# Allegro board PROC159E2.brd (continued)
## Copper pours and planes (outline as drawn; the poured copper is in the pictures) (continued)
DGND on L08_SIG2 (solid shape): 54.38,11.17 54.47,11.11 54.45,11 50.75,7.3 50.67,7.3 50.59,7.35 50.58,7.44 50.58,7.77 50.32,7.98 50.25,8.05 50.27,8.15 52.55,10.43 52.65,10.45 52.72,10.37 53.37,10.17 53.16,10.82 53.08,10.88 53.11,10.99 53.29,11.17
DGND on L08_SIG2 (solid shape): 27.02,32.83 27.11,32.78 27.11,32.68 27.05,32.42 27.18,32.18 27.18,31.84 28.86,30.15 28.89,30.04 28.79,29.98 26.95,29.98 26.86,30.03 26.86,30.14 26.54,30.72 26.22,30.14 26.22,30.03 26.13,29.98 26.05,29.98 24.56,28.49 24.45,28.47 24.39,28.57 24.39,30.43 26.8,32.83
DGND on L08_SIG2 (solid shape): 78.73,45.71 78.8,45.81 78.91,45.79 79.86,44.83 79.86,44.53 79.6,44.53 79.5,44.51 79.42,44.46 79.29,44.32 79.24,44.24 79.22,44.15 79.22,43.96 79.24,43.86 79.29,43.78 79.44,43.63 79.46,43.59 79.44,43.55 79.42,43.54 79.29,43.41 79.24,43.33 79.22,43.23 79.22,43.04 79.24,42.95 79.29,42.87 79.44,42.72 79.46,42.68 79.44,42.64 79.42,42.63 79.29,42.49 79.24,42.41 79.22,42.32 79.22,42.13 79.24,42.03 79.29,41.95 79.44,41.8 79.46,41.76 79.44,41.73 79.42,41.71 79.22,41.51 79.22,41.21 79.24,41.12 79.29,41.04 79.5,40.83 79.86,40.83 79.86,39.87 79.8,39.77 79.69,39.79 78.73,40.75
DGND on L08_SIG2 (solid shape): 80.38,42.49 80.45,42.48 80.58,42.44 80.71,42.44 80.8,42.42 80.84,42.34 80.84,41.48 82.43,39.9 82.43,37.98 82.36,37.89 82.25,37.91 80.89,39.28 80.86,39.37 80.92,39.44 81.09,39.99 80.53,40.09 80.42,40.08 80.36,40.17 80.36,41.05 80.1,41.31 80.29,41.49 80.34,41.58 80.36,41.67 80.36,41.86 80.34,41.96 80.29,42.04 80.16,42.17 80.1,42.22 80.29,42.41 80.32,42.44
DGND on L08_SIG2 (solid shape): 84.84,91.48 84.9,91.49 84.93,91.45 84.93,85.26 82.93,83.26 82.93,82.49 82.87,82.4 82.76,82.41 82.58,82.48 82.38,82.46 82.29,82.47 82.24,82.55 82.24,83.22 82.29,83.3 82.38,83.31 82.9,83.67 82.38,84.03 82.29,84.04 82.24,84.12 82.24,84.34 82.62,84.72 82.62,88.02 82.37,88.26 82.36,88.32 82.41,88.35 82.48,88.35 82.8,88.67 82.8,91.28 82.95,91.43 84.79,91.43
DGND on L08_SIG2 (solid shape): 65.49,30.22 65.56,30.31 65.67,30.29 66.3,29.65 66.33,29.55 66.25,29.48 66.03,29.35 65.95,29.1 65.95,29.08 64.94,28.07 64.94,26.28 63.93,25.27 61.98,25.27 61.88,25.34 61.91,25.45 64.15,27.69 64.15,28.78 64.64,29.26 64.7,29.26 64.8,29.2 64.78,29.09 64.28,28.59 64.28,27.12 63.9,26.74 63.88,26.74 63.61,26.09 64.26,26.36 64.26,26.38 64.78,26.91 64.78,28.39 65.49,29.1
DGND on L08_SIG2 (solid shape): 87.27,25.9 87.33,26 87.44,25.97 91.9,21.51 91.9,20.42 91.98,20.34 92,20.23 91.91,20.17 91.53,20.17 90.67,21.02 90.88,21.23 90.93,21.31 90.95,21.4 90.95,21.59 90.93,21.69 90.88,21.77 90.74,21.9 90.66,21.95 90.57,21.97 90.3,21.97 90.3,22.05 90.3,22.24 90.28,22.33 90.23,22.41 90.09,22.55 90.01,22.6 89.92,22.62 89.65,22.62 89.66,22.69 89.66,22.88 89.64,22.98 89.58,23.06 89.45,23.19 89.37,23.25 89.27,23.27 89.01,23.27 89.01,23.34 89.01,23.53 88.99,23.63 88.94,23.71 88.8,23.84 88.72,23.89 88.63,23.91 88.36,23.91 88.36,23.99 88.36,24.28 88.16,24.49 88.07,24.54 87.98,24.56 87.69,24.56 87.4,24.28 87.33,24.28 87.27,24.34
DGND on L08_SIG2 (solid shape): 105.05,84.35 105.16,84.38 105.23,84.28 105.23,83.67 103.9,82.34 103.81,82.31 103.74,82.36 103.14,82.43 103.21,81.84 103.26,81.76 103.23,81.68 100.66,79.11 97.96,79.11 97.87,79.17 97.89,79.28 101.96,83.35 102.94,83.35 103.02,83.31 103.04,83.22 103.41,82.75 103.78,83.22 103.8,83.31 103.88,83.35 104.05,83.35
DGND on L08_SIG2 (solid shape): 52.4,37.38 52.47,37.35 52.5,37.27 52.83,36.9 53.16,37.27 53.18,37.35 53.26,37.38 53.56,37.38 53.68,37.32 53.81,37.3 53.91,37.24 53.89,37.13 52.01,35.25 49.81,35.25 49.81,35.69 50.78,36.65 50.88,36.68 50.95,36.6 51.59,36.4 51.39,37.05 51.32,37.12 51.34,37.22 51.51,37.38
DGND on L08_SIG2 (solid shape): 84.63,21.78 85.02,21.4 85.1,21.34 85.19,21.32 85.46,21.32 85.46,21.06 85.48,20.97 85.53,20.89 85.66,20.75 85.75,20.7 85.84,20.68 86.1,20.68 86.1,20.41 86.12,20.32 86.18,20.24 86.31,20.1 86.39,20.05 86.49,20.03 86.75,20.03 86.75,19.77 86.77,19.67 86.82,19.59 86.96,19.46 87.04,19.4 87.13,19.39 87.4,19.39 87.4,19.12 87.42,19.03 87.47,18.95 87.6,18.81 87.69,18.76 87.78,18.74 88.04,18.74 88.04,18.47 88.06,18.38 88.12,18.3 88.25,18.16 88.33,18.11 88.43,18.09 88.69,18.09 88.69,17.73 89.28,17.13 89.11,16.96 89.06,16.91 88.87,17.09 88.79,17.15 88.69,17.17 88.51,17.17 88.41,17.15 88.33,17.09 88.2,16.96 88.14,16.88 88.12,16.79 88.12,16.54 87.99,16.54 84.01,20.51 84.01,20.69 84.33,20.69 84.54,20.9 84.59,20.98 84.61,21.08 84.61,21.37 84.4,21.57 84.35,21.63 84.56,21.83 84.63,21.83
DGND on L08_SIG2 (solid shape): 89.73,106.65 89.84,106.65 89.98,106.59 90.14,106.6 90.22,106.58 90.26,106.5 90.26,106.29 90.92,105.63 92.55,105.63 92.72,105.47 92.72,105.4 92.13,104.81 89.01,104.81 88.97,104.84 88.98,104.9 89.03,104.96 89.06,104.96 89.33,105.61 88.68,105.33 88.68,105.31 88.57,105.2 88.52,105.25 88.52,105.28 88.52,105.43 88.45,105.57 88.45,106.44 88.44,106.46 88.42,106.57 88.51,106.63 88.82,106.63 88.89,106.6 88.92,106.53 89.31,106.17 89.68,106.56
DGND on L08_SIG2 (solid shape): 62.58,28.97 62.69,28.99 62.75,28.9 62.75,27.72 61.08,26.04 60.99,26.04 60.91,26.09 60.89,26.18 60.58,26.61 60.27,26.18 60.25,26.09 60.17,26.04 59.08,26.04 59,26.09 58.99,26.18 59,26.31 58.97,26.44 58.97,26.54 59.05,26.59 60.19,26.59 61.63,28.03 61.73,28.05 61.8,27.98 62.44,27.81 62.27,28.45 62.2,28.52 62.22,28.62
DGND on L08_SIG2 (solid shape): outline of 124 points within 38.29,17.52 50.36,25.55
DGND on L08_SIG2 (solid shape): outline of 124 points within 70.25,64.26 74.95,69.84
DGND on L08_SIG2 (solid shape): 40.47,15.62 40.58,15.64 40.65,15.55 40.65,11.43 37.16,7.95 37.08,7.92 37.01,7.96 36.49,8.05 36.38,7.53 36.38,7.43 36.29,7.38 36.26,7.38 35.66,6.77 35.57,6.74 35.5,6.79 34.9,6.86 34.98,6.27 35.02,6.19 35,6.11 34.72,5.83 33.74,5.83 33.65,5.89 33.67,6 36.43,8.77 36.46,8.77 36.84,9.14 36.47,9.53 36.38,9.59 36.4,9.7 40.44,13.74 40.44,15.59
DGND on L08_SIG2 (solid shape): 88.55,83.72 88.64,83.75 88.71,83.69 89,83.47 89.34,83.59 89.46,83.62 89.52,83.52 89.52,83.05 89.7,82.87 89.73,82.75 89.63,82.69 89.4,82.69 89.3,82.68 89.25,82.76 88.6,82.98 88.82,82.33 88.9,82.27 88.88,82.16 86.81,80.1 86.7,80.07 86.64,80.17 86.64,81.81 87.34,82.51 87.42,82.54 87.49,82.49 88.07,82.44 88.02,83.02 87.98,83.1 88.01,83.18
DGND on L08_SIG2 (solid shape): outline of 140 points within 42.05,56.35 46.22,62.71
DGND on L08_SIG2 (solid shape): 103.21,92.47 103.27,92.56 103.38,92.54 104.88,91.05 104.88,87.22 104.81,87.13 104.7,87.15 102.93,86.44 104.7,85.72 104.81,85.75 104.88,85.65 104.88,84.88 104.19,84.19 104.09,84.16 104.02,84.23 103.54,84.45 103.3,83.98 103.28,83.89 103.2,83.85 103.11,83.85 103.03,83.89 103.01,83.98 102.97,84.29 102.72,84.47 102.67,84.48 102.67,85.89 101.94,86.62 101.94,86.95 103.21,88.22
DGND on L08_SIG2 (solid shape): outline of 145 points within 45.07,53.17 59.46,62.38
DGND on L08_SIG2 (solid shape): 57.35,36.17 57.43,36.14 57.45,36.06 57.78,35.7 58.11,36.06 58.14,36.14 58.21,36.17 58.95,36.17 59.03,36.14 59.05,36.06 59.05,36.02 59.05,35.98 59.03,35.9 58.95,35.87 58.32,35.87 57.96,35.51 57.93,35.53 57.58,35.49 57.46,35.15 57.46,35.09 57.3,35.09 57.3,35.15 56.78,35.49 56.98,34.9 57,34.9 57.05,34.85 56.96,34.76 56.94,34.76 56.75,34.66 56.65,34.47 56.65,34.45 56.56,34.36 56.51,34.41 56.51,34.43 56.14,34.76 55.86,34.35 55.86,34.29 55.7,34.29 55.71,34.44 55.7,34.53 55.69,34.56 56.04,34.91 56.04,36.09 56.12,36.17
DGND on L08_SIG2 (solid shape): 36.11,9.3 36.1,9.27 36.09,9.2 36.08,9.14 36.08,9.12 32.66,5.7 32.16,5.7 31.49,5.45 32.16,5.2 32.76,5.2 32.85,5.14 32.83,5.03 32.15,4.34 27.51,4.34 27.43,4.38 27.41,4.47 27.42,4.6 27.38,4.72 27.39,4.82 27.48,4.86 29.47,4.86 30.3,5.69 30.39,5.72 30.46,5.68 31.05,5.61 30.99,6.2 30.94,6.28 30.97,6.36 31.31,6.7 31.46,6.7 31.55,6.64 31.55,6.54 31.87,5.96 32.19,6.54 32.19,6.64 32.28,6.7 33.4,6.7 36.05,9.35
DGND on L08_SIG2 (solid shape): 80.34,38.87 80.4,38.97 80.51,38.95 81.99,37.47 81.99,37.19 81.73,37.19 81.63,37.17 81.55,37.12 81.42,36.98 81.36,36.9 81.35,36.81 81.35,36.62 81.36,36.52 81.42,36.44 81.57,36.29 81.58,36.25 81.57,36.21 81.55,36.2 81.42,36.07 81.36,35.99 81.35,35.89 81.35,35.7 81.36,35.61 81.42,35.53 81.57,35.37 81.58,35.34 81.57,35.3 81.55,35.29 81.42,35.15 81.36,35.07 81.35,34.98 81.35,34.79 81.36,34.69 81.42,34.61 81.57,34.46 81.58,34.42 81.57,34.39 81.55,34.37 81.42,34.24 81.36,34.16 81.35,34.06 81.35,33.87 81.36,33.78 81.42,33.7 81.57,33.55 81.58,33.51 81.57,33.47 81.55,33.46 81.42,33.32 81.36,33.24 81.35,33.15 81.35,32.96 81.36,32.86 81.42,32.78 81.57,32.63 81.58,32.59 81.57,32.56 81.55,32.54 81.32,32.31 80.34,33.29 80.34,36.11 80.4,36.21 80.52,36.18 81.18,36.44 80.52,36.7 80.4,36.67 80.34,36.77
DGND on L08_SIG2 (solid shape): 35.29,5.69 35.4,5.71 35.46,5.61 35.71,5.22 36.15,5.36 36.24,5.41 36.64,5.19 37.04,5.41 37.12,5.36 37.21,5.27 37.33,5.21 37.4,5.14 37.37,5.04 37.1,4.77 37.02,4.74 36.95,4.78 36.37,4.83 36.42,4.25 36.46,4.18 36.43,4.1 36.21,3.88 32.64,3.88 32.54,3.95 32.57,4.06 32.9,4.39 33,4.42 33.07,4.34 33.71,4.16 33.53,4.8 33.46,4.87 33.48,4.97 33.84,5.33 34.92,5.33
DGND on L08_SIG2 (solid shape): 34,52.98 34,51.68 39.12,46.56 39.34,46.56 39.43,46.58 39.51,46.63 39.62,46.73 39.69,46.77 39.77,46.74 40.44,46.08 40.45,46.04 40.44,46.01 40.68,45.38 41.06,45.93 41.07,46.03 41.15,46.08 41.3,46.08 41.39,46.03 41.39,45.93 41.44,45.51 41.86,45.4 41.89,45.41 41.95,45.35 41.79,45.19 40.59,45.19 40.06,45.73 38.96,45.73 38.88,45.77 38.87,45.86 38.35,46.33 38.35,45.63 38.41,45.56 38.38,45.47 37.92,45 37.92,43.91 37.88,43.87 37.85,43.83 37.75,43.86 37.75,46.69 37.27,47.17 37.24,47.25 37.28,47.32 37.29,47.34 37.37,47.42 37.43,47.5 37.45,47.59 37.45,47.81 31.05,54.21 29.93,54.21 29.89,54.3 29.92,54.32 29.95,54.35 32.63,54.35
DGND on L08_SIG2 (solid shape): 33.17,16.04 33.25,16 33.27,15.92 33.5,15.51 33.95,15.63 34.03,15.67 34.11,15.63 34.15,15.59 34.19,15.55 34.23,15.48 34.2,15.4 33.39,14.59 33.3,14.56 33.23,14.62 32.62,14.71 32.72,14.1 32.77,14.03 32.74,13.94 31.61,12.81 30.89,12.81 30.44,12.91 30.23,12.5 30.2,12.42 30.13,12.38 29.28,12.38 29.23,12.43 29.05,12.43 28.85,12.55 28.62,12.54 28.53,12.55 28.48,12.63 28.48,13.36 30.77,15.65 30.85,15.68 30.93,15.64 31.23,15.48 31.54,15.63 31.62,15.67 31.7,15.63 32.15,15.51 32.38,15.92 32.4,16 32.48,16.04
DGND on L08_SIG2 (solid shape): outline of 226 points within 19.91,39.15 24.68,58.68
DGND on L08_SIG2 (solid shape): 63.05,45.65 63.05,45.63 63.17,45.38 63.51,45.28 63.54,45.2 63.54,45.14 63.49,45.14 63.48,45.15 63.05,44.86 63.43,44.5 63.51,44.48 63.54,44.4 63.54,42.86 63.51,42.78 63.43,42.76 63.05,42.38 63.53,42.13 63.56,42.15 63.94,41.77 64.55,41.77 64.63,41.74 64.65,41.66 64.65,41.6 64.63,41.52 64.55,41.49 61.72,41.49 61.64,41.57 61.64,42.8 61.67,42.88 61.75,42.9 62.11,43.25 61.7,43.55 61.64,43.55 61.64,43.71 61.7,43.71 62.11,44.03 61.7,44.35 61.64,44.35 61.64,44.51 61.7,44.51 61.97,44.56 62.11,44.79 62.11,44.81 62.2,44.9 62.25,44.85 62.25,44.83 62.83,44.62 62.53,45.16 62.45,45.18 62.42,45.26 62.42,45.32 62.48,45.32 62.48,45.31 62.76,45.35 62.91,45.59 62.91,45.61 63,45.7
DGND on L08_SIG2 (solid shape): outline of 248 points within 20.25,23.6 32.73,29.48
DGND on L08_SIG2 (solid shape): outline of 247 points within 34.66,20.67 46.02,29.55
DGND on L08_SIG2 (solid shape): outline of 234 points within 43.99,35.32 50.92,41
DGND on L08_SIG2 (solid shape): 48.62,18.86 48.73,18.88 48.79,18.79 49.01,18.44 49.41,18.48 49.52,18.5 49.58,18.4 49.58,16.53 49.45,16.32 49.48,16.07 49.48,15.97 49.39,15.92 47.73,15.92 47.72,15.96 47.22,16.25 47.02,15.71 47.01,15.61 46.93,15.56 46.41,15.56 45.98,15.12 44.31,15.12 43.54,14.35 43.54,14.23 43.48,14.13 43.37,14.15 41.74,13.69 42.84,12.41 42.95,12.36 42.93,12.24 39.97,9.28 39.89,9.25 39.81,9.31 39.73,9.42 39.61,9.49 39.55,9.56 39.57,9.65 41.14,11.23 41.14,15.72 41.52,16.1 41.64,16.12 41.7,16.02 43.41,15.23 42.62,16.94 42.52,17 42.54,17.12 43.32,17.89 47.65,17.89
DGND on L08_SIG2 (solid shape): outline of 243 points within 50.07,16.2 58.07,24.17
DGND on L08_SIG2 (solid shape): outline of 283 points within 50.56,15.56 61.99,24.17
DGND on L08_SIG2 (solid shape): outline of 338 points within 78.46,91.91 85.28,98.82
DGND on L08_SIG2 (solid shape): outline of 337 points within 79.83,98.23 85.31,103.58
DGND on L08_SIG2 (solid shape): outline of 341 points within 89.44,99.79 97.45,104.58
DGND on L08_SIG2 (solid shape): outline of 352 points within 64.04,41.67 68.67,44.51
DGND on L08_SIG2 (solid shape): outline of 99 points within 55.56,37.91 67.53,44.55
DGND on L08_SIG2 (solid shape): outline of 389 points within 100.99,12.89 107.46,32.62
DGND on L08_SIG2 (solid shape): outline of 413 points within 71.61,56.58 86.46,61.64
DGND on L08_SIG2 (solid shape): outline of 480 points within 53.68,57.62 66.6,64.21
DGND on L08_SIG2 (solid shape): outline of 470 points within 70.31,75.35 77.11,91.48
DGND on L08_SIG2 (solid shape): outline of 478 points within 74.02,90.09 80.51,103.56
DGND on L08_SIG2 (solid shape): outline of 467 points within 85.91,94.79 92.68,103.59
DGND on L08_SIG2 (solid shape): outline of 489 points within 28.61,65.34 57.32,69.83
DGND on L08_SIG2 (solid shape): outline of 501 points within 90.17,86.17 96.7,96.55
DGND on L08_SIG2 (solid shape): outline of 557 points within 100.14,78.73 113.74,108.19
DGND on L08_SIG2 (solid shape): outline of 574 points within 10.02,36.68 44.14,76.7
DGND on L08_SIG2 (solid shape): outline of 612 points within 81,59.45 91.74,73.73
DGND on L08_SIG2 (solid shape): outline of 676 points within 14.42,54.49 58.86,77.97
DGND on L08_SIG2 (solid shape): outline of 685 points within 50.15,64.52 63.28,78.8
DGND on L08_SIG2 (solid shape): outline of 761 points within 45.58,3.18 60.25,10.89
DGND on L08_SIG2 (solid shape): outline of 753 points within 15.6,12.87 41.43,33.45
DGND on L08_SIG2 (solid shape): outline of 817 points within 91.52,59.91 101.6,78.64
DGND on L08_SIG2 (solid shape): outline of 838 points within 10.02,2.35 38.82,24.55
DGND on L08_SIG2 (solid shape): outline of 1104 points within 88.9,2.65 113.74,13.09
DGND on L08_SIG2 (solid shape): outline of 1313 points within 78.23,37.34 92.56,61.26
DGND on L08_SIG2 (solid shape): outline of 1364 points within 85.71,14.72 106.52,76.28
DGND on L08_SIG2 (solid shape): outline of 1433 points within 96.21,11.3 113.74,62.65
DGND on L08_SIG2 (solid shape): outline of 1417 points within 53.08,29.9 67.53,40.55
DGND on L08_SIG2 (solid shape): outline of 1482 points within 94.14,29.17 110.66,56.56
DGND on L08_SIG2 (solid shape): outline of 1573 points within 45.01,76.63 62.99,102.06
DGND on L08_SIG2 (solid shape): outline of 1737 points within 41.27,82.53 80.04,108.19
DGND on L08_SIG2 (solid shape): outline of 3870 points within 15.57,26.47 48.19,63.48
DGND on TOP: 91.05,21.2 91.05,19.67 93.21,19.67 93.21,21.2
DGND on TOP: 68.71,98.92 68.71,97.27 75.69,97.27 75.69,98.92
DGND on TOP: 96.77,46.47 96.77,44.31 98.29,44.31 98.29,46.47
DGND on TOP: 100.96,16.12 100.96,18.91 100.07,18.91 99.93,19.05 99.93,20.21 99.12,21.02 99.12,22.79 101.47,25.13 109.34,25.13 109.34,22.09 101.85,22.09 101.85,17.01 105.28,17.01 105.53,16.75 107.18,16.75 107.31,16.88 109.6,16.88 109.6,16.12
DGND on TOP: 108.71,53.33 108.71,47.87 110.74,47.87 110.74,53.33
DGND on TOP: 96.39,12.39 99.56,12.39 99.56,15.86 96.77,15.86 96.13,16.5 95.88,16.5 95.88,15.23 96.39,14.72
DGND on TOP: 91.44,58.15 95.25,58.15 95.25,60.44 93.47,60.44 93.47,59.93 92.45,58.92 91.69,58.92 91.44,58.66
DGND on TOP: 96.77,35.81 96.77,37.97 98.29,37.97 98.29,35.81
DGND on TOP: 103.88,54.22 103.88,47.36 105.91,47.36 105.91,54.22
DGND on BOTTOM: 91.05,36.69 91.05,34.4 98.42,34.4 98.42,36.69
DGND on BOTTOM: 22.35,76.06 22.35,73.01 27.81,73.01 27.81,76.06
DGND on BOTTOM: 90.18,14.71 90.18,12.43 98.84,12.43 98.84,14.71
DGND on BOTTOM: 101.09,33.9 101.09,27.92 108.33,27.92 108.33,33.9
DGND on BOTTOM: 98.93,44.56 98.93,36.69 111.25,36.69 111.25,44.56
DGND on BOTTOM: 99.06,48.25 99.06,47.23 100.33,47.23 100.33,49.01 100.07,49.26 100.07,56.12 97.28,56.12 97.28,50.03
DGND on BOTTOM: 52.19,81.52 52.19,80.63 53.84,80.63 54.73,79.74 54.73,77.97 54.99,77.71 56.68,77.71 58.56,79.59 61.84,79.59 62.47,80.22 62.47,81.36 61.38,82.45 61.38,82.9 61.11,83.17 58.03,83.17 56.38,81.52
DGND on BOTTOM: 101.21,25.24 101.21,22.47 105.79,22.47 105.79,25.24
DGND on BOTTOM: 103.75,43.17 105.66,43.17 105.66,54.22 103.75,54.22 103.75,47.99 103.37,47.61 103.37,43.55
DGND on BOTTOM: 70.86,42.15 70.86,37.96 72.26,37.96 72.26,42.15
DGND on L02_GND1, L09_GND4: 70.35,8.88 70.64,7.84 71.43,7.1 67.88,7.1 67.88,2.53 67.87,2.55 43.25,2.55 43.25,5.2 41.04,7.42 38.82,5.2 38.82,2.35 17.42,2.35 17.42,7.1 13.83,7.1 14.63,7.85 14.93,8.9 14.93,13.3 10.02,13.3 10.02,76.95 10.27,76.7 34.79,76.7 37.97,73.52 45.08,73.52 45.46,73.9 45.46,96.63 44.83,97.27 41.65,97.27 41.27,97.65 41.27,108.19 113.74,108.19 113.74,7.1 112.15,7.1 112.15,2.65 88.9,2.65 88.9,13.3 70.35,13.3
DGND on L04_GND2: 70.35,8.88 70.64,7.84 71.43,7.1 67.88,7.1 67.88,2.54 43.25,2.54 43.25,5.2 41.04,7.42 38.82,5.2 38.82,2.28 38.77,2.33 17.42,2.33 17.42,7.1 13.83,7.1 14.63,7.85 14.93,8.9 14.93,13.3 10.02,13.3 10.02,76.95 10.27,76.7 34.79,76.7 37.97,73.52 45.08,73.52 45.46,73.9 45.46,96.63 44.83,97.27 41.65,97.27 41.27,97.65 41.27,108.19 113.74,108.19 113.74,7.1 112.15,7.1 112.15,2.65 88.9,2.65 88.9,13.3 70.35,13.3
DGND on L07_GND3: 70.35,8.88 70.64,7.84 71.43,7.1 67.88,7.1 67.88,2.54 43.25,2.54 43.25,5.2 41.04,7.42 38.82,5.2 38.82,2.28 38.67,2.43 17.42,2.43 17.42,7.1 13.83,7.1 14.63,7.85 14.93,8.9 14.93,13.3 10.02,13.3 10.02,76.95 10.27,76.7 34.79,76.7 37.97,73.52 45.08,73.52 45.46,73.9 45.46,96.63 44.83,97.27 41.65,97.27 41.27,97.65 41.27,108.19 113.74,108.19 113.74,7.1 112.15,7.1 112.15,2.65 88.9,2.65 88.9,13.3 70.35,13.3
VBUS_MAIN on TOP: 100.83,17.13 100.83,18.15 98.8,18.15 98.55,18.4 98.55,18.91 97.7,19.75 97.7,22 99.06,23.36 99.06,24.12 98.67,24.5 97.91,24.5 96.52,23.1 96.52,18.15 96.26,17.89 95.37,17.89 95.37,17.51 98.04,17.51 98.14,17.42 99.53,17.42 99.81,17.13
VBUS_MAIN on L08_SIG2: 95.75,21.2 95.75,16.75 98.93,16.75 98.93,21.2
VBUS_USBC on TOP: 101.98,22.21 101.98,17.26 105.66,17.26 106.29,17.89 107.69,17.89 107.95,18.15 108.96,18.15 108.96,18.4 107.69,18.4 107.44,18.15 106.17,18.15 106.04,18.28 106.04,20.69 106.17,20.82 107.44,20.82 107.69,20.56 108.96,20.56 108.96,20.94 107.95,20.94 107.69,21.2 106.17,21.2 105.15,22.21
VBUS_USBC on BOTTOM: 101.98,22.22 101.98,18.15 105.41,18.15 105.41,21.72 104.9,22.22
VBUS_USBC on L06_PWR2: 92.07,12.18 92.07,8.88 106.42,8.88 106.42,24.37 97.15,24.37 97.15,17.26
VBUS_XDS110 on TOP: 12.44,95.87 12.44,96.89 14.22,96.89 14.22,100.32 17.78,100.32 17.78,97.02 16.63,95.87
VBUS_XDS110 on L06_PWR2: 22.22,83.68 22.22,104.38 16.63,104.38 14.35,102.1 14.35,84.19 16.25,82.28 20.82,82.28
VCC3V3_XDS on TOP: 18.16,97.65 22.98,97.65 22.98,100.32 18.16,100.32
VCC3V3_XDS on L05_PWR1: 10.02,77.85 10.02,108.19 40.64,108.19 40.64,97.02 41.02,96.63 44.32,96.63 44.57,96.38 44.57,74.41 38.86,74.41 35.49,77.77 10.09,77.77 ; 1 cut-out
VCC_1V2 on TOP: 81.18,50.52 81.18,46.94 84.45,46.94 84.45,50.52
VCC_1V2 on BOTTOM: 81.25,49.87 81.25,46.94 84.71,46.94 84.71,49.87
VCC_1V2 on L05_PWR1: 85.21,49.14 85.21,44.31 77.34,36.44 69.21,36.44 66.47,33.7 57.75,33.7 55.4,36.05 55.4,37.29 55.24,37.45 54.1,37.45 54.1,46.47 57.53,49.9 84.45,49.9 ; 1 cut-out
VCC_1V8_LDO4 on BOTTOM: 105.79,55.49 105.79,48.37 107.06,48.37 107.06,55.49
VCC_1V8_LDO4 on L06_PWR2: 38.86,23.61 38.86,22.09 49.91,22.09 53.46,25.64 53.46,28.69 53.97,29.2 91.82,29.2 99.18,36.56 109.05,36.56 111.6,34.02 113.53,34.02 113.53,45.2 108.96,49.77 106.29,49.77 105.53,49.01 105.53,47.49 88.39,30.34 53.08,30.34 46.35,23.61
VCC_5V0 on L06_PWR2: 64.38,4.05 67.18,4.05 67.18,7.73 66.04,8.88 20.19,8.88 19.3,9.77 19.3,19.04 16.12,22.21 16.12,23.74 17.01,24.63 21.46,24.63 24,22.09 25.01,22.09 25.27,22.34 25.27,25.39 24.76,25.9 15.36,25.9 14.22,24.75 14.22,15.48 16.51,13.2 16.51,9 17.9,7.61 43.34,7.61 46.86,4.09 64.35,4.09 64.38,4.06
VCC_6V0_BBOUT on TOP: 100.83,47.36 100.83,49.77 100.58,50.03 100.58,53.94 99.92,54.6 97.91,54.6 96.77,53.45 96.77,51.4 92.98,47.61 92.32,47.61 90.67,45.96 90.17,45.96 90.17,50.66 91.05,51.55 92.39,51.55 94.36,53.52 94.36,55.61 92.32,57.65 91.31,57.65 91.31,57.9 100.45,57.9 100.81,57.54 100.81,55.51 101.98,54.34 101.98,53.33 101.85,53.2 101.85,47.36
VCC_6V0_BBOUT on BOTTOM: 100.45,56.25 100.45,49.52 100.71,49.26 100.71,47.1 100.45,46.85 100.45,44.95 101.34,44.95 101.34,46.09 101.91,46.66 101.91,56.25
VCC_PLDO1 on BOTTOM: 107.06,36.18 107.06,33.13 109.34,33.13 111.25,35.04 111.25,36.18
VCC_PLDO2 on TOP: 106.55,53.07 106.55,45.2 108.33,45.2 108.33,53.07
VCC_PLDO2 on BOTTOM: 107.56,51.3 107.56,48.25 109.34,48.25 109.34,50.15 112.77,50.15 113.41,50.79 113.41,52.72 113.2,52.93 111.49,52.93 110.88,52.31 108.58,52.31
VDD1V1A on L06_PWR2: 83.94,78.47 83.94,68.19 94.23,68.19 94.23,70.6 89.66,75.17 89.53,75.17 86.23,78.47
VDD2V5A on TOP: 91.82,73.88 91.82,66.92 94.48,66.92 94.48,73.88
VDD_2V5 on TOP: 93.09,76.31 93.09,74.28 96.13,74.28 96.13,76.31
VDD_2V5 on TOP: 69.27,89.4 69.27,88 71.24,88 71.37,88.13 72.77,88.13 72.77,88.76 71.88,88.76 71.24,89.4
VDD_2V5 on TOP: 101.34,83.77 101.34,81.2 102.89,81.2 105.41,83.71 105.41,87.5 102.62,87.5 102.62,84.44 101.95,83.77
VDD_2V5 on BOTTOM: 100.84,86.37 100.84,80.31 103.98,80.31 103.98,85 104.89,85.92 104.89,87.36 102.7,87.36 101.71,86.37
VDD_2V5 on L05_PWR1: 87.24,73.52 76.07,84.7 69.21,84.7 69.21,89.4 76.96,89.4 79.37,86.98 79.37,85.17 82.47,82.07 85.36,82.07 88.96,78.47 95.88,78.47 95.88,73.52 ; 1 cut-out
VDD_2V5 on L06_PWR2: 96.9,74.19 105.38,82.67 105.38,89.93 102.48,92.82 91.94,92.82 92.07,92.7 92.07,84.19 94.61,81.65 94.61,74.71 95.13,74.19
VDD_5V0_LDO3 on BOTTOM: 10.02,59.3 10.02,61.71 12.19,61.71 12.19,59.3
VDD_5V0_LDO3 on BOTTOM: 103.75,33.9 103.75,30.98 108.07,30.98 108.07,32.75 105.41,32.75 105.15,33.01 105.15,33.9
VDD_5V0_LDO3 on L06_PWR2: 50.02,70.6 17.65,70.6 10.66,63.61 10.66,59.8 10.73,59.74 10.73,59.68 11.55,59.68 12.57,60.69 14.73,60.69 22.6,68.57 51.68,68.57 53.36,70.24 60.85,70.24 69.08,78.47 72.6,78.47 73.27,77.8 73.27,75.68 74.29,75.68 74.29,77.84 72.26,79.87 67.1,79.87 63.67,76.44 55.86,76.44
VDD_IO_3V3 on BOTTOM: 102.36,59.3 102.36,57.96 107.44,57.96 107.44,59.3
VDD_IO_3V3 on BOTTOM: 68.52,41.64 68.52,37.83 70.35,37.83 70.35,42.15 69.03,42.15
VDD_IO_3V3 on L06_PWR2: 50.54,44.56 50.54,38.85 53.59,35.8 53.59,35.67 55.37,35.67 55.62,35.93 55.62,37.07 54.99,37.71 54.99,40.25 56.13,41.39 56.26,41.39 56.26,44.82 57.02,45.58 57.4,45.58 58.29,44.69 58.29,44.56 58.67,44.18 63.75,44.18 64.26,44.69 65.4,44.69 65.91,44.18 65.91,43.29 64.51,41.9 64.51,38.34 65.78,37.07 65.78,36.94 65.4,36.56 65.4,34.28 65.53,34.15 78.35,34.15 82.29,38.09 93.59,38.09 106.93,51.42 106.93,58.66 106.17,59.42 101.98,59.42 92.83,50.28 56.26,50.28
VDD_MMC1 on TOP: 15.74,58.15 15.74,55.74 24.25,55.74 24.25,58.15
VDD_MMC1 on L05_PWR1: 20.95,57.26 20.95,50.41 24.63,50.41 24.63,57.26
VDDA1V8_OSC_PLL_F on L03_SIG1: 55.31,34.67 55.9,34.67 55.9,36.02 54.27,36.02 53.2,34.71 53.2,32.8 50.02,29.61 50.02,28.87 49.26,28.12 49.26,28.12 49.26,27.66 49.38,27.54 50.17,27.54 50.68,28.05 50.68,28.81 54.33,32.46 54.33,33.7
VDDA3V3_F on L06_PWR2: 57.4,37.2 57.4,35.67 59.28,35.67 59.28,35.35 59.59,35.04 59.59,32.08 60.57,31.1 70.35,31.1 71.37,32.12 71.37,32.88 71.02,33.23 70.32,33.23 69.08,31.99 63.07,31.99 62.04,33.02 62.04,36.56 61.4,37.2
VDDA_IO_1V8 on BOTTOM: 58.23,35.91 58.23,34.63 59.75,34.63 60.4,33.98 62.11,33.98 62.36,34.22 62.36,35.91
VDDA_IO_1V8 on L06_PWR2: 33.14,26.4 31.49,24.75 31.49,23.74 32,23.23 33.52,23.23 34.41,24.12 39.87,24.12 39.94,24.18 45.65,24.18 52.32,30.85 57.15,30.85 59.09,32.79 59.09,35.16 58.7,35.55 56.89,35.55 56.64,35.29 56.64,33.39 56.07,32.82 56,32.88 53.34,32.88 51.94,34.28 50.67,34.28 48.32,31.93 48.32,29.39 45.33,26.4
VDDA_IO_3V3 on L06_PWR2: 65.91,14.97 65.91,25.26 53.46,25.26 49.78,21.58 31.49,21.58 28.57,24.5 26.03,24.5 26.03,22.21 23.36,19.55 23.36,16.24 21.71,14.59 21.71,14.21 23.24,12.69 63.62,12.69
VDDIO on TOP: 69.46,97.27 69.46,95.75 72.77,95.75 72.77,97.27
VDDIO on TOP: 83.31,65.39 85.6,65.39 85.6,66.68 85.2,66.68 84.83,67.04 84.83,67.68 84.39,68.12 83.31,68.12
VDDIO on BOTTOM: 90.65,81.44 90.65,82.95 88.49,82.95 88.49,81.44
VDDIO on L06_PWR2: 68.96,97.27 68.96,91.68 74.67,85.97 74.67,61.96 95.37,61.96 95.5,61.84 99.18,61.84 99.69,61.33 99.69,59.55 99.82,59.42 100.71,59.42 100.83,59.55 100.83,69.96 97.79,73.01 95.5,73.01 93.98,74.54 93.98,80.51 91.44,83.05 91.44,91.3 91.05,91.68 76.32,91.68 72.77,95.24 72.77,97.14 72.64,97.27
VDDS_IO_1V8 on L06_PWR2: 55.88,37.45 55.88,35.55 55.24,34.91 54.48,34.91 53.97,35.42 44.57,35.42 41.65,32.5 41.65,30.72 42.03,30.34 42.67,30.34 42.92,30.59 42.92,31.74 44.51,33.32 48.27,33.32 49.86,34.91 52.57,34.91 53.97,33.52 55.62,33.52 56.19,34.09 56.19,35.36 56.89,36.06 56.89,37.2 57.53,37.83 61.72,37.83 62.46,37.09 62.46,33.42 63.64,32.25 68.58,32.25 69.08,32.75 69.08,33.64 68.96,33.77 67.31,33.77 67.18,33.9 65.15,33.9 64.64,34.4 64.64,36.06 65.15,36.56 65.15,37.07 64.13,38.09 64.13,42.02 65.27,43.17 65.27,44.18 65.15,44.31 64.64,44.31 64.13,43.8 58.42,43.8 57.15,45.07 56.89,45.07 56.64,44.82 56.64,41.26 55.37,39.99 55.37,37.96
(no net) on TOP: 17.42,2.35 17.42,7.1 13.83,7.1 14.63,7.85 14.93,8.9 14.93,13.3 10.02,13.3 10.02,76.95 10.27,76.7 34.79,76.7 37.97,73.52 45.08,73.52 45.46,73.9 45.46,96.63 44.83,97.27 41.65,97.27 41.27,97.65 41.27,108.19 113.74,108.19 113.74,7.1 112.15,7.1 112.15,2.65 88.9,2.65 88.9,13.3 70.35,13.3 70.35,8.88 70.64,7.84 71.43,7.1 67.88,7.1 67.88,2.53 67.87,2.55 43.25,2.55 43.25,5.2 41.04,7.42 38.82,5.2 38.82,2.35 ; 97 cut-outs
(no net) on BOTTOM: 17.42,2.35 17.42,7.1 13.83,7.1 14.63,7.85 14.93,8.9 14.93,13.3 10.02,13.3 10.02,76.95 10.27,76.7 34.79,76.7 37.97,73.52 45.08,73.52 45.46,73.9 45.46,96.63 44.83,97.27 41.65,97.27 41.27,97.65 41.27,108.19 113.74,108.19 113.74,7.1 112.15,7.1 112.15,2.65 88.9,2.65 88.9,13.3 70.35,13.3 70.35,8.88 70.64,7.84 71.43,7.1 67.88,7.1 67.88,2.53 67.87,2.55 43.25,2.55 43.25,5.2 41.04,7.42 38.82,5.2 38.82,2.35 ; 124 cut-outs
(no net) on L03_SIG1: 17.42,2.35 17.42,7.1 13.83,7.1 14.63,7.85 14.93,8.9 14.93,13.3 10.02,13.3 10.02,76.95 10.27,76.7 34.79,76.7 37.97,73.52 45.08,73.52 45.46,73.9 45.46,96.63 44.83,97.27 41.65,97.27 41.27,97.65 41.27,108.19 113.74,108.19 113.74,7.1 112.15,7.1 112.15,2.65 88.9,2.65 88.9,13.3 70.35,13.3 70.35,8.88 70.64,7.84 71.43,7.1 67.88,7.1 67.88,2.53 67.87,2.55 43.25,2.55 43.25,5.2 41.04,7.42 38.82,5.2 38.82,2.35 ; 233 cut-outs
(no net) on L08_SIG2: 67.88,7.1 67.88,2.53 67.87,2.55 43.25,2.55 43.25,5.2 41.04,7.42 38.82,5.2 38.82,2.35 17.42,2.35 17.42,7.1 13.83,7.1 14.63,7.85 14.93,8.9 14.93,13.3 10.02,13.3 10.02,76.95 10.27,76.7 34.79,76.7 37.97,73.52 45.08,73.52 45.46,73.9 45.46,96.63 44.83,97.27 41.65,97.27 41.27,97.65 41.27,108.19 113.74,108.19 113.74,7.1 112.15,7.1 112.15,2.65 88.9,2.65 88.9,13.3 70.35,13.3 70.35,8.88 70.64,7.84 71.43,7.1 ; 251 cut-outs
ADC_DAC-VREF on TOP: 35.52,27.01 35.52,24.28 37.73,24.28 37.73,27.01
ADC_DAC-VREF on BOTTOM: 28.25,25.29 28.25,23.37 36.12,23.37 36.12,25.29
ADC_VREF1 on BOTTOM: 28.2,23.2 28.2,21.67 31.61,21.67 31.61,23.2
ADC_VREF2 on BOTTOM: 27.49,26.34 27.49,25.37 30.54,25.37 30.54,26.34
ADC_VREF3 on BOTTOM: 33.14,23.15 33.14,21.81 36.15,21.81 36.15,23.15
AM263_DAC_VREF on BOTTOM: 33.06,26.36 33.06,25.42 36.2,25.42 36.2,26.36
AM263_DAC_VREF0 on TOP: 27.94,27.59 27.94,24.99 32.86,24.99 32.86,27.59
ETH_EARTH on TOP: 102.23,78.09 102.23,59.93 113.75,59.93 113.75,78.09
ETH_EARTH on BOTTOM: 102.23,78.09 102.23,59.93 113.74,59.93 113.74,78.09 ; 1 cut-out
ETH_EARTH on L02_GND1, L03_SIG1, L04_GND2, L05_PWR1, L06_PWR2, L07_GND3, L08_SIG2, L09_GND4: 102.23,78.09 102.23,59.93 113.15,59.93 113.15,78.09
HSEC_5V0 on TOP: 90.55,19.29 90.55,18.53 92.07,18.53 93.09,17.51 95.12,17.51 95.12,17.89 94.1,17.89 93.85,18.15 93.85,18.66 93.21,19.29
HSEC_5V0 on BOTTOM: 88.39,20.05 88.39,18.58 92.83,18.58 92.83,20.05
HSEC_5V0 on L05_PWR1: 30.73,2.65 30.73,10.27 32.25,11.8 55.49,11.8 60.45,16.75 88.13,16.75 89.02,15.86 91.94,15.86 92.58,16.5 92.58,18.41 92.47,18.52 90.81,18.52 90.55,18.78 90.55,19.67 90.67,19.67 90.67,20.31 95.75,25.39 98.67,25.39 102.99,21.07 102.99,12.81 105.28,10.53 112.39,10.53 112.39,5.58 94.36,5.58 89.28,10.66 89.28,13.22 88.41,14.08 71.24,14.08 69.21,12.05 69.21,7.1 67.88,7.1 67.88,2.65 43.25,2.65 43.25,5.2 41.04,7.42 38.82,5.2 38.82,2.65
OPSI_DQS on BOTTOM: 31.34,44.47 31.34,42.01 32.82,42.01 32.82,44.47
USBC_EARTH on TOP, L03_SIG1, L04_GND2, L05_PWR1: 106.04,11.8 106.04,15.74 110.61,15.74 110.61,23.23 106.8,23.23 106.29,23.74 106.29,25.51 113.79,25.51 113.79,11.8
USBC_EARTH on BOTTOM: 106.04,11.8 106.04,15.74 110.61,15.74 110.61,23.23 106.8,23.23 106.29,23.74 106.29,25.51 113.79,25.51 113.79,11.8
USBC_EARTH on L02_GND1, L06_PWR2, L07_GND3: 106.04,11.8 106.04,15.74 110.61,15.74 110.61,23.23 106.8,23.23 106.29,23.74 106.29,25.51 113.78,25.51 113.78,11.8
USBC_EARTH on L08_SIG2, L09_GND4: 106.04,11.8 106.04,15.74 110.61,15.74 110.61,23.23 106.8,23.23 106.29,23.74 106.29,25.51 113.79,25.51 113.79,11.8
VMAIN on TOP: 92.96,15.23 93.47,15.74 93.47,16.37 93.85,16.75 96.52,16.75 97.02,16.24 99.49,16.24 99.49,17.13 92.83,17.13 91.82,18.15 90.44,18.15 90.12,18.47 90.12,19.14 87.88,19.14 87.88,16.09 88.74,15.23
VMAIN on TOP: 53.34,78.11 53.34,77.23 53.88,77.23 54.1,77.02 54.1,72.06 57.88,68.28 57.88,65.96 58.31,65.53 58.31,63.67 58.47,63.51 58.99,63.51 59.15,63.68 59.15,66.24 59.69,66.78 59.69,67.99 59.19,68.49 59.19,69.8 56.03,72.96 56.03,77.56 55.48,78.11
VMAIN on BOTTOM: 90,18.02 90,15.1 98.67,15.1 98.67,18.02
VMAIN on BOTTOM: 97.42,90.48 97.42,86.94 100.09,86.94 100.09,90.48
VMAIN on BOTTOM: 53.84,80.38 53.84,79.32 53.33,78.81 53.29,78.85 52.77,78.85 52.7,78.79 52.7,77.49 53.05,77.14 55,77.14 55.24,77.38 55.24,77.71 55.11,77.84 55.11,78.47 54.1,79.49 54.1,80.38
VMAIN on L05_PWR1: 89.4,16.5 91.82,16.5 91.94,16.62 91.94,18.02 90.55,18.02 90.04,18.53 90.04,21.83 94.23,26.02 102.61,26.02 113.53,36.94 113.53,56.63 110.74,59.42 102.99,59.42 101.47,60.95 101.47,93.59 92.83,102.22 78.1,102.22 75.31,99.43 67.05,99.43 53.46,85.84 53.46,76.95 55.24,76.95 55.37,77.08 55.37,78.22 56.95,79.81 56.95,85.27 67.75,96.06 76,96.06 79.12,99.17 90.04,99.17 96.39,92.82 96.39,61.84 103.37,54.85 107.26,54.85 110.73,51.38 110.73,44.46 109.8,43.53 109.8,38.16 107.31,35.67 106.17,35.67 99.31,28.82 92.58,28.82 87.75,23.99 87.75,18.15
VMAIN on L06_PWR2: 92.32,17.39 92.32,25.39 88.9,28.82 54.22,28.82 53.72,28.31 53.72,27.04 54.73,26.02 82.8,26.02 87.37,21.45 87.37,17.39
VMAIN_12V0 on TOP: 89.91,34.28 89.91,27.55 88.51,26.15 88.51,22.47 89.15,21.83 94.86,21.83 95.85,22.82 95.85,27.06 94.86,28.05 94.86,34.28
VMAIN_12V0 on L06_PWR2: 16.76,23.86 16.76,22.85 19.81,19.8 19.81,11.93 21.84,9.89 66.82,9.89 70.5,13.58 92.58,13.58 96.64,17.64 96.64,26.02 100.71,30.09 100.71,34.15 100.58,34.28 98.42,34.28 93.09,28.94 93.09,17.26 92.32,16.5 85.97,16.5 83.82,18.66 83.82,20.43 78.86,25.39 70.1,25.39 66.8,22.09 66.8,14.47 64.13,11.8 22.73,11.8 21.2,13.32 21.2,14.85 22.35,15.99 22.35,20.31 21.59,21.07 21.2,21.07 21.2,22.21 19.55,23.86
VMAINP_12V0 on TOP: 99.9,28.65 101.53,30.28 101.53,35.1 101.85,35.42 101.85,38.09 100.58,38.09 100.58,35.67 99.06,34.15 95.25,34.15 95.25,28.65
VMAINP_12V0 on BOTTOM: 100.33,28.02 100.33,29.78 100.96,30.42 100.96,33.83 91.09,33.83 91.09,31.75 94.81,28.02
VPP_1V7 on TOP: 84.96,46.6 84.96,45.04 85.55,44.45 86.38,44.45 86.38,45.83 87.49,45.83 87.63,45.96 88.51,45.96 88.51,46.6
VPP_R on L05_PWR1: 50.54,37.07 50.54,35.67 54.86,35.67 54.86,37.07
VSYS_1V2 on TOP: 82.99,52.46 82.99,51.12 86.33,51.12 86.33,52.13 86.54,52.33 87.9,52.33 88.16,52.59 88.16,54.24 89.14,55.23 90.03,55.23 90.8,55.99 90.8,57.14 89.78,57.14 89.27,56.62 84.85,56.62 84.85,54.33
VSYS_1V2 on BOTTOM: 82.17,51.83 82.17,50.33 84.79,50.33 84.8,50.34 84.8,50.65 86.28,52.13 86.28,54.44 84.78,54.44
VSYS_1V2_SW on TOP: 84.85,58.95 84.85,57.01 91.05,57.01 91.05,57.52 90.03,57.52 88.59,58.95
VSYS_3V3_LDO1 on TOP: 102.45,54.45 102.45,44.31 103.34,44.31 103.34,49.74 103.75,50.15 103.75,56.88 101.62,56.88 101.24,56.5 101.24,55.66
VSYS_3V3_LDO1 on BOTTOM: 62.61,12.69 62.61,9.89 66.23,9.89 67.45,11.12 67.45,12.69
VSYS_3V3_LDO1 on BOTTOM: 102.23,57.58 102.23,47.6 104.01,47.6 104.01,57.58
VSYS_3V3_LDO1 on L05_PWR1: 10.02,13.3 10.02,108.19 113.74,108.19 113.74,43.76 109.41,39.42 108.9,39.42 98.86,29.39 92.01,29.39 80.07,17.45 60.18,17.45 56.03,13.3 ; 6 cut-outs
VSYS_3V3_LDO1 on L06_PWR2: 73.02,93.21 73.02,108.19 101.72,108.19 101.72,93.21
VSYS_3V3_LDO2 on TOP: 11.04,58.79 11.04,56.76 14.73,56.76 14.73,58.79
VSYS_3V3_LDO2 on TOP: 102.48,37.2 102.48,34.79 103.5,34.79 103.63,34.66 103.63,34.28 104.14,34.28 104.14,35.67 104.01,35.8 103.12,35.8 103.12,37.2
VSYS_3V3_LDO2 on BOTTOM: 101.47,38.21 101.47,34.25 105.02,34.25 105.02,38.21
VSYS_3V3_LDO2 on L03_SIG1: 103.59,36.95 103.59,34.17 105.62,34.17 105.62,36.95
VSYS_3V3_LDO2 on L06_PWR2: 11.68,59.17 11.68,49.64 24.25,37.07 24.25,27.04 37.71,27.04 37.71,36.82 53.21,52.31 87.88,52.31 88.51,52.95 88.51,61.33 74.42,61.33 72.77,62.98 72.77,77.56 72.36,77.97 69.46,77.97 69.21,77.71 69.21,73.83 64.43,69.05 54.6,69.05 52.84,67.3 22.35,67.3 15.24,60.19 12.7,60.19
VSYS_TA_3V3 on BOTTOM: 44.83,102.98 44.83,101.46 45.21,101.07 45.21,97.66 45.22,97.65 46.35,97.65 46.35,102.98
VSYS_TA_3V3 on BOTTOM: 54.35,82.66 54.35,81.9 56.13,81.9 57.79,83.56 61.34,83.56 61.34,87.57 55.65,87.57 55.25,87.17 55.25,83.56
VSYS_TA_3V3 on L06_PWR2: 43.3,108.06 43.3,99.05 46.22,96.13 46.22,74.79 44.32,72.89 17.01,72.89 16.25,72.12 16.25,71.87 16.89,71.23 48.89,71.23 54.73,77.08 63.47,77.08 67.75,81.36 67.75,108.06
VSYS_TA_3V3_SW on BOTTOM: 53.84,82.03 54.1,82.03 54.1,83.28 54.78,83.96 54.78,87.42 54.58,87.62 52.95,87.62 52.7,87.36 52.7,83.81 53.84,82.66
XDS_GND on TOP: 10.02,77.71 10.02,108.19 40.64,108.19 40.64,97.02 41.27,96.38 44.57,96.38 44.57,74.92 43.94,74.28 38.86,74.28 38.86,74.41 35.56,77.71 ; 2 cut-outs
XDS_GND on TOP: 10.02,84.7 10.02,88 14.47,88 14.47,84.7
XDS_GND on BOTTOM: 10.41,87.87 10.41,85.2 14.09,85.2 14.09,87.87
XDS_GND on BOTTOM: 21.84,80.51 21.84,78.22 27.68,78.22 27.68,80.51
XDS_GND on BOTTOM: 10.02,77.84 10.02,106.43 11.78,108.19 40.64,108.19 40.64,96.63 44.32,96.63 44.57,96.38 44.57,74.94 44.6,74.94 44.06,74.41 38.92,74.41 35.49,77.84 ; 2 cut-outs
XDS_GND on L02_GND1, L03_SIG1, L04_GND2, L07_GND3, L09_GND4: 10.02,77.85 10.02,108.19 40.64,108.19 40.64,97.02 41.02,96.63 44.32,96.63 44.57,96.38 44.57,74.41 38.86,74.41 35.49,77.77 10.09,77.77 ; 1 cut-out
XDS_GND on L06_PWR2: 10.02,77.85 10.02,108.19 40.64,108.19 40.64,97.02 41.02,96.63 44.32,96.63 44.57,96.38 44.57,74.41 38.86,74.41 35.49,77.77 10.09,77.77 ; 2 cut-outs
XDS_GND on L08_SIG2: 10.02,77.85 10.02,108.19 40.64,108.19 40.64,97.02 41.02,96.63 44.32,96.63 44.57,96.38 44.57,74.41 38.86,74.41 35.49,77.77 10.09,77.77 ; 6 cut-outs
XDS_SHIELD on TOP, L02_GND1, L03_SIG1, L04_GND2, L05_PWR1, L06_PWR2, L07_GND3, L08_SIG2, L09_GND4: 9.27,99.43 9.27,88.63 13.58,88.63 13.58,92.82 11.68,92.82 11.68,97.27 13.71,97.27 13.71,99.43
XDS_SHIELD on BOTTOM: 9.27,99.43 9.27,88.63 13.58,88.63 13.58,92.82 11.68,92.82 11.68,97.27 13.71,97.27 13.71,99.43 ; 1 cut-out
N32995608 on BOTTOM: 96.75,87.07 96.75,80.34 99.32,80.34 99.32,86.56 101.66,86.56 101.66,87.07
N34755833 on TOP: 98.55,36.32 98.55,38.09 99.31,38.09 99.31,36.45 99.56,36.19 99.56,35.94 99.31,35.69 98.67,35.69 98.42,35.94 98.42,36.19
N34755833 on BOTTOM: 91.56,40.75 91.56,39.1 94.61,39.1 96.89,36.82 97.66,36.82 98.68,35.8 99.82,35.8 99.82,37.71 98.93,38.6 98.93,40.75
N34755845 on TOP: 98.55,45.96 98.55,44.31 99.31,44.31 99.31,45.83 99.56,46.09 99.56,46.34 99.31,46.6 98.67,46.6 98.42,46.34 98.42,46.09
N34755845 on BOTTOM: 94.74,45.83 94.74,41.27 98.84,41.27 98.84,43.21 100.07,44.44 100.07,46.72 98.29,46.72 98.29,45.96 98.17,45.83
N34780660 on BOTTOM: 99.54,65.82 99.54,61.5 101.57,61.5 101.57,65.82
N35053522 on TOP: 81.3,15.79 86.1,15.79 86.1,18.66 87.07,19.62 87.07,25.6 82.43,25.6 81.3,24.47
N35053536 on TOP: 75.58,23.99 75.58,21.07 78.48,21.07 79.58,22.17 80.89,22.17 80.89,23.99 79.24,23.99 79.24,23.99

Small or netless copper shapes (teardrops, artwork), in the pictures only: 413 on TOP, 426 on BOTTOM, 186 on L03_SIG1, 1 on L06_PWR2, 208 on L08_SIG2

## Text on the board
Ref Des/Assembly Bottom: PROC159E2 ASSEMBLY BOTTOM REV E2
Ref Des/Silkscreen Bottom: B | C | A | FOR EVALUATION ONLY; | NOT FCC APPROVED FOR RESALE | ASSY
User.Comments: CR_1_2 | CR_1_1 | BOARD NAME: | AM263P CC | REV: E2 | DATE: 28/09/23 | DESCRIPTION: | SHEET | OF | 17 | PROC159E2 | SCALE: 1 | TEXAS INSTRUMENTS
Ref Des/Assembly Top: PROC159E2 ASSEMBLY TOP REV E2
Ref Des/Silkscreen Top: OPN# | SL# | PCB#: PROC159E2
PAGE_OUTLINE: LAYOUT BY | REVIEWED BY | APPROVED BY | SIGNATURES | AMB | KK | ZA | DATE | 280923 | SCALE: | SIZE | D | NONE | TEXAS INSTRUMENTS | SHEET 1 OF 17 | PROC159E2 | Rev | E2
DISPLAY_TOP: 19. | 18. | 16. | 17. | ALL BOARD OUTLINE INNER ANGLES THAT ARE NOT EXPLICITY DIMENTIONED SHALL BE WITH TOOL PATH 1.0MM DIA OR SMALLER. | EDGE FINGERS SHALL HAVE HARD GOLD FINISH. | ENSURE UL REGISTERED E-FILE NUMBER SHALL BE PRINTED ON THE PCB SILKSCREEN. | VIA ON PAD SHALL BE RESIN FILLED AND CAP-PLATED.
User.16: TITLE: | MISTRAL | AM62A AUTOMOTIVE RGMII | R | #60, ADARSH REGENT, 100'FT RING ROAD, | MISTRAL SOLUTIONS PVT.LTD., | DOMLUR EXTENSION, BANGALORE-560 071 | TOP ASSEMBLY OF PROC151E1 | 8 | A | 5 | 4 | 28 | SK-ETH-AUTO-DCO2 | PROC151E1 | 9 | 19 | 3 | 2 | SHEET    OF 13 | 50 | 49 | BOTTOM ASSEMBLY OF PROC151E1 | DATE: | 20AUG22 | REV | E1 | SCALE: 1
User.17: 8 | 5 | 4 | 28 | 9 | 19 | 3 | 2 | 50 | 49 | A | SK-ETH-AUTO-DCO2 | PROC151E1 | R | TOP ASSEMBLY OF PROC151E1 | BOTTOM ASSEMBLY OF PROC151E1 | TITLE: | AM62A AUTOMOTIVE RGMII | #60, ADARSH REGENT, 100'FT RING ROAD, | MISTRAL SOLUTIONS PVT.LTD., | DOMLUR EXTENSION, BANGALORE-560 071 | SHEET    OF 13 | DATE: | 20AUG22 | REV | E1 | SCALE: 1 | MISTRAL
User.45: 03 | 04 | 05 | 06 | STRIPLINE | MICROSTRIP | EDGE COUPLED STRIPLINE | EDGE COUPLED MICROSTRIP | L3,L8 | L1,L10 | L8 | 3.6 | 5.8 | 4.2 | 3.7 | NA | 4.4 | 6 | 50 | 90 | L2/L4,L7/L9 | L2,L9 | L7/L9 | FIGURE | SIZE | 8.0 | 36.0 | 40.0 | 44.0 | 66.0 | 32.0 | 108.0 | 126.0 | 62.0x24.0 | 76.0x28.0 | 82.0x24.0 | DRILL CHART: TOP to BOTTOM | ALL UNITS ARE IN MILS | TOLERANCE | +3.0/-3.0 | +2.0/-2.0 | PLATED | NON-PLATED | QTY | 2196 | 14 | 18 | 12 | 22 | 2 | 21 | 11 | 6 - Provide serial numbers to the assembled boards for identification. | 7 - The assembled board are wrapped in ESD Covers(individual) and packed securely before shipment. | ASSEMBLY NOTES:- | 1 - All MSL components should be baked as per JEDEC standard. | 2 - PCB should be baked at 120 degree for 8 hours. | 3 - Board assembly must comply with workmanship standards IPC-A-610 Class 2, unless otherwise specified. | 4 - These assemblies are ESD sensitive, ESD precautions shall be observed. | 5 - These assemblies must be clean and free from flux and all contaminants. Use of no clean flux is not acceptable. | PROC101 E2 ASSEMBLY TOP | PROC101 E2 ASSEMBLY BOTTOM
